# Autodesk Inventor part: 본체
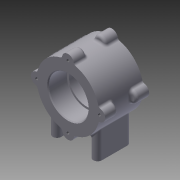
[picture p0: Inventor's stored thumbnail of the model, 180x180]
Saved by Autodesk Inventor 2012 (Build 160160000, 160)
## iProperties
Created: 2015-03
Part Number: 본체
Material: 알루미늄-6061
Document SubType Name: Modeling
Designer: Owner
Density: 2.71 g/cm^3
Mass: 450.772 g
Surface Area: 332.692 cm^2
Volume: 166.337 cm^3
Author: Owner
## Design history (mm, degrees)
sketch "스케치1"
  geometry: C1 r 37 at (0, 0); 1 further point
  constraints: 1 centre point, 1 coincident
  dimensions: "d0" = 74 diameter of C1
extrude "돌출1" new body sketch "스케치1" stored distance "d1" = 52; taper "d2" = 0 deg
sketch "스케치2"
  geometry: L1 (-37, 26)-(37, 26) reference; L2 (37, -26)-(-37, -26) reference; L3 (37, -26)-(37, 26) reference; L4 (-37, -26)-(-37, 26) reference; L5 (0, 26)-(0, -26); L6 (23.5, 26)-(23.5, 4); L7 (23.5, 4)-(21, 4); L8 (21, 4)-(21, -4); L9 (21, -4)-(23.5, -4); L10 (23.5, -4)-(23.5, -26); 2 further points
  constraints: 12 end point, 4 parallel, 3 midpoint, 2 collinear, 2 point on line, 1 coincident, 1 perpendicular, 1 vertical alignment
  dimensions: "d3" = 22 distance of L6.start L6.end; "d4" = 47 diameter of L6 L5; "d5" = 42 diameter of L8 L5
revolve "회전1" sketch "스케치2" stored, may be unused: angle "d6" = 90 deg
sketch "스케치3"
  geometry: C1 r 23.5 at (0, 0) reference; A1 r 37 centre (0, 0) between (-37, 0) and (-36.338, 6.969) reference; A2 r 7 centre (-37, 0) between (-36.338, 6.969) and (-36.338, -6.969)
  constraints: 5 point on circle, 1 centre point, 1 horizontal alignment
  dimensions: "d7" = 7 radius of A2
extrude "돌출2" join sketch "스케치3" distance "d8" = 15; taper "d9" = 0 deg
sketch "스케치4"
  geometry: C1 r 23.5 at (0, 0) reference; 1 further point
  constraints: 1 vertical alignment
  dimensions: "d13" = 37 distance of C1.centre point (0, 37)
hole "구멍1" sketch "스케치4" at (0, 37) diameter "d14" = 3.242; stored, may be unused: countersink angle "d18" = 90 deg, drill point angle "d20" = 118 deg; dims "d15" = 8, "d16" = 4, "d17" = 2, "d19" = 11
node "작업 평면1"
node "작업 평면2"
sketch "스케치5"
  geometry: L1 (19, 15)-(19, -15); L2 (29, -15)-(29, 15); A1 r 5 centre (24, -15) between (19, -15) and (29, -15); A2 r 5 centre (24, 15) between (29, 15) and (19, 15); 2 further points
  constraints: 4 end point, 4 point on circle, 4 tangent, 2 centre point, 1 horizontal alignment, 1 midpoint, 1 parallel, 1 vertical
  dimensions: "d25" = 40 dimension on A1 A2; "d26" = 24 horizontal distance of A1.centre point (0, 0); "d27" = 5 radius of A2
extrude "돌출3" join sketch "스케치5" stored distance "d28" = 15; taper "d29" = 0 deg
sketch "스케치6"
  geometry: A1 r 5 centre (24, -15) between (19, -15) and (29, -15) reference; A2 r 5 centre (24, 15) between (29, 15) and (19, 15) reference; 3 further points
  constraints: 2 coincident
hole "구멍2" sketch "스케치6" at (24, 15), (24, -15) diameter "d30" = 4.134; stored, may be unused: countersink angle "d34" = 90 deg, drill point angle "d36" = 118 deg; dims "d31" = 6, "d32" = 4, "d33" = 2, "d35" = 8
node "작업 평면4"
  node "작업 평면3"
sketch "스케치7"
  geometry: 2 further points
  constraints: 1 coincident, 1 other
feature "엠보싱1" sketch "스케치7" dims "d39" = 0.5, "d40" = 0
chamfer "모따기1" distance "d41" = 1; stored, may be unused: second distance "d42" = 2, angle "d43" = 45 deg
fillet "모깎기1" dims "d44" = 3
fillet "모깎기2" dims "d45" = 3
fillet "모깎기3" dims "d46" = 3
node "작업 평면5"
fillet "모깎기4" dims "d47" = 0.3
fillet "모깎기5" dims "d48" = 3
fillet "모깎기6" dims "d49" = 3
sketch "스케치8"
  geometry: L1 (-4.49, 8.981)-(3.344, 8.981); L2 (3.344, 8.981)-(3.344, -9.554); L3 (3.344, -9.554)-(-4.49, -9.554); L4 (-4.49, -9.554)-(-4.49, 8.981); 1 further point
  constraints: 8 end point, 2 parallel, 1 horizontal, 1 perpendicular
extrude "돌출4" join sketch "스케치8" stored distance "d50" = 10; taper "d51" = 0 deg
node "솔리드1"
pattern_circular "원형 패턴1" dims angle "d11" = 360 deg
pattern_circular "원형 패턴2" dims angle "d22" = 360 deg
mirror "대칭1"
mirror "대칭2"
mirror "대칭3"
mirror "대칭4"
mirror "대칭5"
mirror "대칭6"
other parameters: "d24" = -56, "d37" = -45 deg
